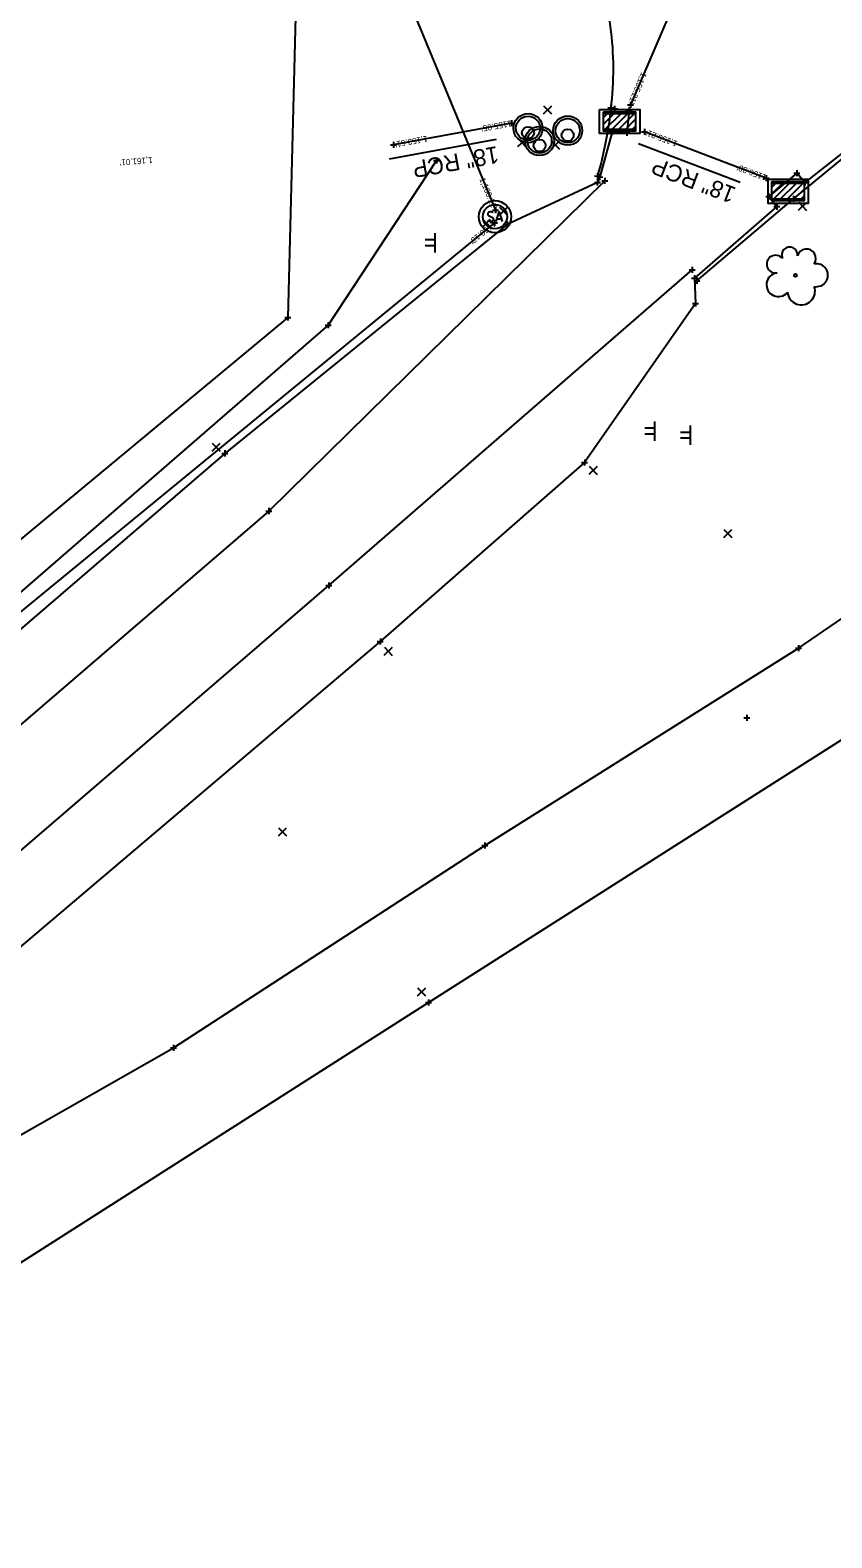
# Model space of a CAD drawing. Extents: x 142461 to 147261, y 511126 to 514697.
# Drawn here: x 145149.5 to 145282.5, y 513373.9 to 513623.9 of the extents above; entities that cross this region are included whole.
import ezdxf

# ---------------------------------------------------------------- set-up
doc = ezdxf.new("R2010")
doc.units = 0
for name, color, linetype in [('DR_X_Cells', 7, 'Continuous'), ('DR_X_Elev_Flow', 7, 'Continuous'), ('DR_X_Storm_Sewer', 7, 'Continuous'), ('DR_X_Text', 7, 'Continuous'), ('GK_Drainage_Nodes', 7, 'Continuous'), ('PM_X_Surveyed_Line', 7, 'Continuous'), ('PV_X_Curb', 7, 'Continuous'), ('PV_X_EOP', 7, 'Continuous'), ('SC_Scratch1', 7, 'Continuous'), ('SN_X_Public', 7, 'Continuous'), ('SV_X_Original_Ground', 7, 'Continuous'), ('SV_X_Random_Point', 7, 'Continuous'), ('SV_X_Shot_Marker', 7, 'Continuous'), ('SV_X_Toe_of_Slope', 7, 'Continuous'), ('SV_X_Top_of_Bank', 7, 'Continuous'), ('UT_X_Sanitary_Cells', 7, 'Continuous'), ('UT_X_Sanitary_Line', 7, 'Continuous'), ('VG_X_Cells', 7, 'Continuous'), ('VG_X_Tree_Line_Lt', 7, 'Continuous')]:
    doc.layers.add(name, color=color, linetype=linetype)

msp = doc.modelspace()

# ---------------------------------------------------------------- linework, layer by layer
at = {"layer": 'DR_X_Cells'}
for p, q in [((145244.6, 513607.16), (145247.78, 513610.34)), ((145244.6, 513608.29), (145246.65, 513610.34)), ((145244.6, 513609.42), (145245.52, 513610.34)), ((145245.68, 513607.12), (145248.91, 513610.34)), ((145246.82, 513607.12), (145249.93, 513610.23)), ((145247.95, 513607.12), (145249.93, 513609.1)), ((145249.08, 513607.12), (145249.93, 513607.97)), ((145272.55, 513595.6), (145275.74, 513598.78)), ((145272.55, 513596.73), (145274.6, 513598.78)), ((145272.55, 513597.86), (145273.47, 513598.78)), ((145273.64, 513595.55), (145276.87, 513598.78)), ((145274.77, 513595.55), (145277.89, 513598.67)), ((145275.9, 513595.55), (145277.89, 513597.53)), ((145277.03, 513595.55), (145277.89, 513596.4))]:
    msp.add_line(p, q, dxfattribs=at)
for points in [[(145243.93, 513610.73), (145250.6, 513610.73), (145250.6, 513606.73), (145243.93, 513606.73)], [(145244.6, 513610.34), (145249.93, 513610.34), (145249.93, 513607.12), (145244.6, 513607.12)], [(145244.6, 513610.06), (145249.93, 513610.06), (145249.93, 513607.4), (145244.6, 513607.4)], [(145271.89, 513599.16), (145278.55, 513599.16), (145278.55, 513595.16), (145271.89, 513595.16)], [(145272.55, 513598.78), (145277.89, 513598.78), (145277.89, 513595.55), (145272.55, 513595.55)], [(145272.55, 513598.5), (145277.89, 513598.5), (145277.89, 513595.83), (145272.55, 513595.83)]]:
    msp.add_lwpolyline(points, close=True, dxfattribs=at)
for centre, radius in [((145232.08, 513607.62), 2.42), ((145232.08, 513607.62), 2), ((145238.66, 513607.22), 2.42), ((145238.66, 513607.22), 2), ((145232.08, 513606.87), 1), ((145234, 513605.5), 2.42), ((145234, 513605.5), 2), ((145238.66, 513606.47), 1), ((145234, 513604.75), 1)]:
    msp.add_circle(centre, radius, dxfattribs=at)
at = {"layer": 'DR_X_Elev_Flow'}
for p, q in [((145248.6, 513611.47), (145249.6, 513611.47)), ((145249.1, 513611.97), (145249.1, 513610.97)), ((145249.1, 513611.47), (145249.1, 513611.47)), ((145229.36, 513608.93), (145229.36, 513607.93)), ((145228.86, 513608.43), (145229.86, 513608.43)), ((145229.36, 513608.43), (145229.36, 513608.43)), ((145250.88, 513607.03), (145251.88, 513607.03)), ((145251.38, 513607.53), (145251.38, 513606.53)), ((145251.38, 513607.03), (145251.38, 513607.03)), ((145271.06, 513599.35), (145272.06, 513599.35)), ((145271.56, 513599.85), (145271.56, 513598.85)), ((145271.56, 513599.35), (145271.56, 513599.35))]:
    msp.add_line(p, q, dxfattribs=at)
at = {"layer": 'DR_X_Storm_Sewer'}
for p, q in [((145273.93, 513669.58), (145249.1, 513611.47)), ((145229.36, 513608.43), (145209.74, 513604.85)), ((145271.56, 513599.35), (145251.38, 513607.03))]:
    msp.add_line(p, q, dxfattribs=at)
at = {"layer": 'DR_X_Text'}
for p, q in [((145209.09, 513602.55), (145226.84, 513605.79)), ((145250.4, 513605.1), (145267.27, 513598.68))]:
    msp.add_line(p, q, dxfattribs=at)
at = {"layer": 'GK_Drainage_Nodes'}
for p, q in [((145232.08, 513609.62), (145232.08, 513609.62)), ((145238.66, 513609.22), (145238.66, 513609.22)), ((145244.6, 513608.73), (145244.6, 513608.73)), ((145247.27, 513610.73), (145247.27, 513610.73)), ((145247.27, 513610.06), (145247.27, 513610.06)), ((145247.27, 513608.73), (145247.27, 513608.73)), ((145247.27, 513608.73), (145247.27, 513608.73)), ((145249.93, 513608.73), (145249.93, 513608.73)), ((145232.08, 513607.62), (145232.08, 513607.62)), ((145232.08, 513607.62), (145232.08, 513607.62)), ((145232.08, 513606.87), (145232.08, 513606.87)), ((145234, 513607.5), (145234, 513607.5)), ((145238.66, 513607.22), (145238.66, 513607.22)), ((145238.66, 513607.22), (145238.66, 513607.22)), ((145238.66, 513606.47), (145238.66, 513606.47)), ((145247.27, 513607.4), (145247.27, 513607.4)), ((145247.27, 513607.12), (145247.27, 513607.12)), ((145247.27, 513606.73), (145247.27, 513606.73)), ((145232.08, 513605.62), (145232.08, 513605.62)), ((145234, 513605.5), (145234, 513605.5)), ((145234, 513605.5), (145234, 513605.5)), ((145234, 513604.75), (145234, 513604.75)), ((145238.66, 513605.22), (145238.66, 513605.22)), ((145234, 513603.5), (145234, 513603.5)), ((145275.22, 513599.16), (145275.22, 513599.16)), ((145272.55, 513597.16), (145272.55, 513597.16)), ((145275.22, 513598.5), (145275.22, 513598.5)), ((145275.22, 513597.16), (145275.22, 513597.16)), ((145275.22, 513597.16), (145275.22, 513597.16)), ((145277.89, 513597.16), (145277.89, 513597.16)), ((145226.62, 513594.94), (145226.62, 513594.94)), ((145275.22, 513595.83), (145275.22, 513595.83)), ((145275.22, 513595.55), (145275.22, 513595.55)), ((145275.22, 513595.16), (145275.22, 513595.16)), ((145226.6, 513592.94), (145226.6, 513592.94)), ((145226.6, 513592.94), (145226.6, 513592.94)), ((145226.6, 513592.94), (145226.6, 513592.94)), ((145226.58, 513590.94), (145226.58, 513590.94))]:
    msp.add_line(p, q, dxfattribs=at)
for centre in [(145232.08, 513607.62), (145238.66, 513607.22), (145234, 513605.5), (145226.6, 513592.94)]:
    msp.add_circle(centre, 2, dxfattribs=at)
at = {"layer": 'PM_X_Surveyed_Line'}
for points in [[(145244.8, 513598.91), (145189.1, 513544.15), (145118.95, 513483.86), (145022.54, 513402.94), (144981.98, 513369.93), (144853.86, 513268.93), (144843.13, 513260.73), (144805.16, 513232.38), (144766.25, 513204.67), (144725.33, 513176.3), (144684.91, 513148.47), (144644.29, 513120.74), (144603.48, 513093.63), (144562.1, 513066.23), (144520.96, 513039), (144479.14, 513010.91), (144437.33, 512982.92), (144395.18, 512954.5), (144353.44, 512926.48), (144318.54, 512903.34), (144276.1, 512875.34), (144232.02, 512845.98), (144188.92, 512817.39), (144145.08, 512788.07)], [(144863.53, 513255.94), (144992.11, 513357.76), (145033.02, 513390.91), (145129.2, 513471.78), (145199.04, 513531.8), (145259.33, 513584.12)]]:
    msp.add_lwpolyline(points, dxfattribs=at)
at = {"layer": 'PV_X_Curb'}
msp.add_lwpolyline([(145260.07, 513582.32), (145276.14, 513595.9), (145290.04, 513607.37), (145356.39, 513650.72), (145444.8, 513707.03), (145524.93, 513758.25), (145602.45, 513807.43), (145635.85, 513828.51)], dxfattribs=at)
msp.add_open_spline([(145241.47, 513638.88), (145243.17, 513635.15), (145246.14, 513626.19), (145246.47, 513612.52), (145244.7, 513603.43), (145243.59, 513599.69)], degree=3, dxfattribs=at)
at = {"layer": 'PV_X_EOP'}
for p, q in [((145246.44, 513610.82), (145248.85, 513610.61)), ((145248.85, 513610.61), (145248.47, 513606.86)), ((145246.04, 513607.03), (145243.97, 513599.53)), ((145248.47, 513606.86), (145246.04, 513607.03)), ((145243.97, 513599.53), (145243.58, 513598.63)), ((145243.58, 513598.63), (145228.64, 513591.65)), ((145228.64, 513591.65), (145181.78, 513553.71)), ((145181.78, 513553.71), (145111.31, 513493.11))]:
    msp.add_line(p, q, dxfattribs=at)
msp.add_lwpolyline([(145289.66, 513607.81), (145278.01, 513598.6), (145276.66, 513600.17), (145272.01, 513596.3), (145273.34, 513594.61), (145259.72, 513582.73), (145259.85, 513578.53), (145241.47, 513552.18), (145207.57, 513522.52), (145136.67, 513462.42), (145040.82, 513381.46), (145013.06, 513360.46), (145002.34, 513355.98), (144995.52, 513354.02), (144864.91, 513253.13), (144870.59, 513243.84), (144959.33, 513299.47), (145056.87, 513361.54), (145139.95, 513414.46), (145215.58, 513462.65), (145285.89, 513507.37)], dxfattribs=at)
at = {"layer": 'SN_X_Public'}
for p, q in [((145216.64, 513589.09), (145215.04, 513589.09)), ((145216.64, 513590.21), (145216.64, 513587.01)), ((145216.64, 513588.13), (145215.04, 513588.13)), ((145216.64, 513588.61), (145216.64, 513588.61)), ((145253.08, 513558.98), (145253.08, 513555.78)), ((145253.08, 513557.86), (145251.48, 513557.86)), ((145253.08, 513556.9), (145251.48, 513556.9)), ((145253.08, 513557.38), (145253.08, 513557.38)), ((145258.98, 513557.19), (145257.38, 513557.19)), ((145258.98, 513556.23), (145257.38, 513556.23)), ((145258.98, 513558.31), (145258.98, 513555.11)), ((145258.98, 513556.71), (145258.98, 513556.71))]:
    msp.add_line(p, q, dxfattribs=at)
at = {"layer": 'SV_X_Original_Ground'}
msp.add_lwpolyline([(144853.86, 513268.93), (144863.53, 513255.94), (144864.91, 513253.13), (144870.59, 513243.84), (144959.33, 513299.47), (145056.87, 513361.54), (145139.95, 513414.46), (145215.58, 513462.65), (145285.89, 513507.37), (145368.16, 513559.73), (145452.44, 513613.25), (145537.78, 513667.71), (145623.97, 513722.57), (145710.71, 513777.95), (145799.7, 513834.74), (145881.69, 513886.93), (145970.86, 513943.75), (146060.64, 514001.13), (146137.55, 514051.63), (146134.78, 514057.05), (146132.28, 514060.58), (146129.15, 514064.67), (146123.97, 514079.6), (146211.14, 514122.87)], dxfattribs=at)
at = {"layer": 'SV_X_Random_Point'}
for p, q in [((145234.66, 513610), (145236.01, 513611.32)), ((145234.67, 513611.34), (145235.99, 513609.99)), ((145230.41, 513604.56), (145231.76, 513605.88)), ((145230.42, 513605.9), (145231.74, 513604.55)), ((145235.94, 513604.19), (145237.29, 513605.51)), ((145235.96, 513605.52), (145237.28, 513604.17)), ((145227.34, 513593.19), (145228.69, 513594.51)), ((145227.35, 513594.53), (145228.67, 513593.18)), ((145276.97, 513594.01), (145278.32, 513595.33)), ((145276.98, 513595.34), (145278.3, 513594)), ((145224.5, 513591.21), (145225.85, 513592.53)), ((145224.52, 513592.54), (145225.84, 513591.19)), ((145179.68, 513554.06), (145181.03, 513555.38)), ((145179.7, 513555.39), (145181.02, 513554.05)), ((145242.23, 513550.25), (145243.58, 513551.57)), ((145242.24, 513551.58), (145243.56, 513550.23)), ((145264.54, 513539.77), (145265.87, 513541.1)), ((145264.54, 513541.1), (145265.87, 513539.77)), ((145208.24, 513520.23), (145209.58, 513521.55)), ((145208.25, 513521.56), (145209.57, 513520.21)), ((145190.68, 513490.28), (145192.01, 513491.62)), ((145190.68, 513491.62), (145192.01, 513490.28)), ((145213.76, 513463.77), (145215.11, 513465.09)), ((145213.77, 513465.11), (145215.09, 513463.76))]:
    msp.add_line(p, q, dxfattribs=at)
at = {"layer": 'SV_X_Shot_Marker'}
for p, q in [((145245.83, 513611.51), (145245.81, 513610.51)), ((145246.45, 513611.32), (145246.44, 513610.32)), ((145245.32, 513611.01), (145246.32, 513611)), ((145245.82, 513611.01), (145245.82, 513611.01)), ((145245.94, 513610.83), (145246.94, 513610.82)), ((145246.44, 513610.82), (145246.44, 513610.82)), ((145248.35, 513610.61), (145249.35, 513610.6)), ((145248.85, 513611.11), (145248.84, 513610.11)), ((145248.85, 513610.61), (145248.85, 513610.61)), ((145245.54, 513607.03), (145246.54, 513607.02)), ((145246.05, 513607.53), (145246.03, 513606.53)), ((145246.04, 513607.03), (145246.04, 513607.03)), ((145247.97, 513606.87), (145248.97, 513606.86)), ((145248.48, 513607.36), (145248.47, 513606.36)), ((145248.47, 513606.86), (145248.47, 513606.86)), ((145209.24, 513604.85), (145210.24, 513604.85)), ((145209.74, 513605.35), (145209.74, 513604.35)), ((145209.74, 513604.85), (145209.74, 513604.85)), ((145216.4, 513602.26), (145217.4, 513602.26)), ((145216.9, 513602.76), (145216.9, 513601.76)), ((145216.9, 513602.26), (145216.9, 513602.26)), ((145243.09, 513599.7), (145244.09, 513599.69)), ((145243.47, 513599.53), (145244.47, 513599.52)), ((145243.59, 513599.13), (145243.57, 513598.13)), ((145243.59, 513600.19), (145243.58, 513599.19)), ((145243.59, 513599.69), (145243.59, 513599.69)), ((145243.97, 513600.03), (145243.96, 513599.03)), ((145243.97, 513599.53), (145243.97, 513599.53)), ((145244.3, 513598.91), (145245.3, 513598.9)), ((145244.81, 513599.41), (145244.79, 513598.41)), ((145244.8, 513598.91), (145244.8, 513598.91)), ((145276.16, 513600.18), (145277.16, 513600.17)), ((145276.67, 513600.67), (145276.66, 513599.67)), ((145276.66, 513600.17), (145276.66, 513600.17)), ((145278.01, 513599.1), (145278, 513598.1)), ((145243.08, 513598.64), (145244.08, 513598.63)), ((145243.58, 513598.63), (145243.58, 513598.63)), ((145271.51, 513596.31), (145272.51, 513596.3)), ((145272.02, 513596.8), (145272.01, 513595.8)), ((145272.01, 513596.3), (145272.01, 513596.3)), ((145276.14, 513596.4), (145276.13, 513595.4)), ((145277.51, 513598.61), (145278.51, 513598.6)), ((145278.01, 513598.6), (145278.01, 513598.6)), ((145226.16, 513594.02), (145227.16, 513594.02)), ((145226.66, 513594.52), (145226.66, 513593.52)), ((145226.66, 513594.02), (145226.66, 513594.02)), ((145272.84, 513594.62), (145273.84, 513594.61)), ((145273.35, 513595.11), (145273.34, 513594.11)), ((145273.34, 513594.61), (145273.34, 513594.61)), ((145275.64, 513595.91), (145276.64, 513595.9)), ((145276.14, 513595.9), (145276.14, 513595.9)), ((145226.03, 513591.91), (145227.03, 513591.91)), ((145226.53, 513592.41), (145226.53, 513591.41)), ((145226.53, 513591.91), (145226.53, 513591.91)), ((145228.14, 513591.66), (145229.14, 513591.64)), ((145228.64, 513592.15), (145228.63, 513591.15)), ((145228.64, 513591.65), (145228.64, 513591.65)), ((145258.83, 513584.13), (145259.83, 513584.12)), ((145259.33, 513584.62), (145259.32, 513583.62)), ((145259.33, 513584.12), (145259.33, 513584.12)), ((145259.22, 513582.74), (145260.22, 513582.73)), ((145259.57, 513582.33), (145260.57, 513582.31)), ((145259.72, 513583.23), (145259.71, 513582.23)), ((145259.72, 513582.73), (145259.72, 513582.73)), ((145260.08, 513582.82), (145260.07, 513581.82)), ((145260.07, 513582.32), (145260.07, 513582.32)), ((145259.85, 513579.03), (145259.84, 513578.03)), ((145191.73, 513576.24), (145192.73, 513576.23)), ((145192.23, 513576.73), (145192.22, 513575.73)), ((145192.23, 513576.23), (145192.23, 513576.23)), ((145259.35, 513578.54), (145260.35, 513578.53)), ((145259.85, 513578.53), (145259.85, 513578.53)), ((145198.44, 513574.98), (145199.44, 513574.98)), ((145198.94, 513575.48), (145198.94, 513574.48)), ((145198.94, 513574.98), (145198.94, 513574.98)), ((145181.28, 513553.71), (145182.28, 513553.7)), ((145181.78, 513554.21), (145181.77, 513553.21)), ((145181.78, 513553.71), (145181.78, 513553.71)), ((145240.97, 513552.19), (145241.97, 513552.18)), ((145241.48, 513552.68), (145241.47, 513551.68)), ((145241.47, 513552.18), (145241.47, 513552.18)), ((145188.6, 513544.15), (145189.6, 513544.14)), ((145189.1, 513544.65), (145189.09, 513543.65)), ((145189.1, 513544.15), (145189.1, 513544.15)), ((145198.54, 513531.81), (145199.54, 513531.8)), ((145199.05, 513532.3), (145199.04, 513531.3)), ((145199.04, 513531.8), (145199.04, 513531.8)), ((145207.07, 513522.52), (145208.07, 513522.51)), ((145207.58, 513523.02), (145207.57, 513522.02)), ((145207.57, 513522.52), (145207.57, 513522.52)), ((145276.47, 513521.4), (145277.47, 513521.4)), ((145276.97, 513521.9), (145276.97, 513520.9)), ((145276.97, 513521.4), (145276.97, 513521.4)), ((145267.89, 513509.86), (145268.89, 513509.85)), ((145268.4, 513510.35), (145268.39, 513509.35)), ((145268.39, 513509.85), (145268.39, 513509.85)), ((145224.92, 513489.17), (145224.92, 513488.17)), ((145224.42, 513488.67), (145225.42, 513488.67)), ((145224.92, 513488.67), (145224.92, 513488.67)), ((145215.08, 513462.66), (145216.08, 513462.65)), ((145215.59, 513463.15), (145215.58, 513462.15)), ((145215.58, 513462.65), (145215.58, 513462.65)), ((145172.77, 513455.16), (145173.77, 513455.16)), ((145173.27, 513455.66), (145173.27, 513454.66)), ((145173.27, 513455.16), (145173.27, 513455.16))]:
    msp.add_line(p, q, dxfattribs=at)
at = {"layer": 'SV_X_Toe_of_Slope'}
msp.add_lwpolyline([(145119.62, 513424.61), (145173.27, 513455.16), (145224.92, 513488.67), (145276.97, 513521.4), (145328.93, 513556.92), (145380.26, 513589.74), (145431.18, 513623.07), (145480.29, 513655.45), (145533.69, 513687.8), (145582.02, 513724.74), (145628.84, 513766.74), (145660.19, 513809.96), (145712.81, 513840.49)], dxfattribs=at)
at = {"layer": 'SV_X_Top_of_Bank'}
msp.add_lwpolyline([(145216.9, 513602.26), (145198.94, 513574.98), (145066.09, 513459.78), (144977.8, 513381.92), (144941.22, 513354.92), (144938.7, 513352.73)], dxfattribs=at)
at = {"layer": 'UT_X_Sanitary_Cells'}
for points in [[(145226.27, 513593.63), (145226.25, 513593.66), (145226.21, 513593.68), (145226.1, 513593.72), (145225.96, 513593.75), (145225.86, 513593.75), (145225.82, 513593.75), (145225.65, 513593.72), (145225.52, 513593.64), (145225.43, 513593.54), (145225.4, 513593.44), (145225.4, 513593.36), (145225.42, 513593.26), (145225.52, 513593.17), (145226.21, 513592.79), (145226.27, 513592.74), (145226.3, 513592.69), (145226.32, 513592.61), (145226.32, 513592.54), (145226.31, 513592.46), (145226.3, 513592.41), (145226.27, 513592.35), (145226.24, 513592.3), (145226.22, 513592.26), (145226.18, 513592.22), (145226.14, 513592.2), (145226.09, 513592.17), (145226.05, 513592.16), (145225.94, 513592.15), (145225.76, 513592.15), (145225.65, 513592.18), (145225.49, 513592.27), (145225.39, 513592.34)], [(145226.8, 513592.14), (145227.32, 513593.74), (145227.79, 513592.13)], [(145227.67, 513592.51), (145226.93, 513592.52)]]:
    msp.add_lwpolyline(points, dxfattribs=at)
for radius in [2.67, 2]:
    msp.add_circle((145226.6, 513592.94), radius, dxfattribs=at)
at = {"layer": 'UT_X_Sanitary_Line'}
for p, q in [((145182.95, 513699.65), (145226.66, 513594.02)), ((145226.53, 513591.91), (145051.16, 513448.16))]:
    msp.add_line(p, q, dxfattribs=at)
at = {"layer": 'VG_X_Cells'}
msp.add_circle((145276.46, 513583.22), 0.24, dxfattribs=at)
for centre, radius, start, end in [((145273.15, 513585.08), 1.47, 39.0625, 279.5412), ((145275.48, 513586.58), 1.32, 354.0047, 205.9741), ((145278.29, 513586.05), 1.55, 323.83, 165.0376), ((145279.92, 513583.25), 1.91, 259.1453, 101.4596), ((145273.61, 513581.67), 1.97, 96.1722, 320.5737), ((145277.41, 513580.61), 2.28, 184.9476, 19.4572)]:
    msp.add_arc(centre, radius, start, end, dxfattribs=at)
at = {"layer": 'VG_X_Tree_Line_Lt'}
msp.add_lwpolyline([(145193.73, 513634.84), (145192.23, 513576.23), (145025.85, 513438.22), (145019.15, 514007.47)], dxfattribs=at)

# ---------------------------------------------------------------- texts
at = {"layer": 'DR_X_Text'}
for rotation, p in [(190.3412, (145226.93, 513604.68)), (159.1564, (145266.77, 513597.69))]:
    msp.add_text('18" RCP', height=2.8, rotation=rotation, dxfattribs=at).set_placement(p)
at = {"layer": 'SC_Scratch1'}
for s, rotation, p in [("1,155.21'", 246.8585, (145250.91, 513616.99)), ("1155.05'", 190.3412, (145229.27, 513608.92)), ("1,153.61'", 190.3412, (145215.33, 513606.38)), ("1,155.21'", 159.1564, (145256.96, 513605.44)), ("1,161.01'", 184.8298, (145169.77, 513602.85)), ("1156.38'", 159.1564, (145271.74, 513599.81)), ("1,160.11'", 292.4779, (145223.99, 513599.17)), ("1160.13'", 219.3426, (145226.22, 513592.3))]:
    msp.add_text(s, height=1, rotation=rotation, dxfattribs=at).set_placement(p)

doc.saveas('drawing.dxf')
